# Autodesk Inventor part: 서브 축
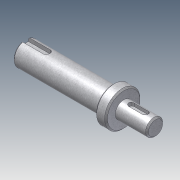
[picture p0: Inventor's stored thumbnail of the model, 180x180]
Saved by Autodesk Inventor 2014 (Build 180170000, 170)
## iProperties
Company: 한국ATC센터
Created: 2014-10
Part Number: 서브 축
Document SubType Name: Modeling
Designer: KYOUNG IL JANG
Density: 1 g/cm^3
Mass: 19.9624 g
Surface Area: 57.7178 cm^2
Volume: 19.9624 cm^3
Material: Generic
Appearance: Metal-Steel (Stainless, Brushed)
Author: KYOUNG IL JANG
Revision Number: 1
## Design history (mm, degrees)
revolve "회전1" stored, may be unused: angle "d5" = 90 deg
chamfer "모따기1" distance "d6" = 1; stored, may be unused: second distance "d7" = 2, angle "d8" = 45 deg
node "작업 평면1"
sketch "스케치2"
  geometry: L1 (11.25, 5)-(11.25, -5) reference; L2 (-5.75, -2)-(4.25, -2); L3 (4.25, 2)-(-5.75, 2); A1 r 2 centre (4.25, 0) between (4.25, -2) and (4.25, 2); A2 r 2 centre (-5.75, 0) between (-5.75, 2) and (-5.75, -2); 2 further points
  constraints: 4 end point, 4 point on circle, 4 tangent, 2 centre point, 1 horizontal alignment, 1 midpoint, 1 parallel, 1 perpendicular
  dimensions: "d9" = 4 distance between parallel lines of L2 L3; "d10" = 14 dimension on A1 A2; "d11" = 5 distance edge to line of A1 L1
extrude "돌출1" cut sketch "스케치2" distance "d12" = 2.5; taper "d13" = 0 deg
node "작업 평면2"
sketch "스케치3"
  geometry: L1 (-31.166, -7.5)-(-31.166, 7.5) reference; L2 (-31.166, 2.5)-(-15.666, 2.5); L3 (-15.666, -2.5)-(-31.166, -2.5); A1 r 2.5 centre (-15.666, 0) between (-15.666, -2.5) and (-15.666, 2.5); 2 further points
  constraints: 4 end point, 2 perpendicular, 2 point on circle, 2 point on line, 2 tangent, 1 centre point, 1 horizontal alignment, 1 midpoint
  dimensions: "d14" = 5 distance between parallel lines of L3 L2; "d15" = 18 dimension on A1 L1
extrude "돌출2" cut sketch "스케치3" distance "d16" = 3; taper "d17" = 0 deg
node "솔리드1"
sketch "스케치1"
  geometry: L1 (-16.331, 0)-(-108.831, 0); L2 (-16.331, 0)-(-16.331, -6); L3 (-16.331, -6)-(-38.831, -6); L4 (-38.831, -12.5)-(-46.5, -12.5); L5 (-46.5, -8.5)-(-108.831, -8.5); L6 (-108.831, -8.5)-(-108.831, 0); L7 (-46.5, -8.5)-(-46.5, -12.5); L8 (-38.831, -6)-(-38.831, -12.5); L9 (-46.5, 12.249)-(-46.5, -12.249) reference; L10 (-38.831, -17)-(-38.831, 17) reference; 2 further points
  constraints: 17 end point, 4 perpendicular, 2 collinear, 2 parallel, 1 horizontal, 1 midpoint, 1 point on line
  dimensions: "d1" = 12 diameter of L3 L1; "d2" = 25 diameter of L4 L1; "d3" = 17 diameter of L5 L1; "d4" = 62.33128 distance of L5.start L5.end (derived); "d18" = 22.5 distance of L2.end L3.end; "d20" = 70 distance between parallel lines of L6 L8
node "참조4"
node "참조5"
